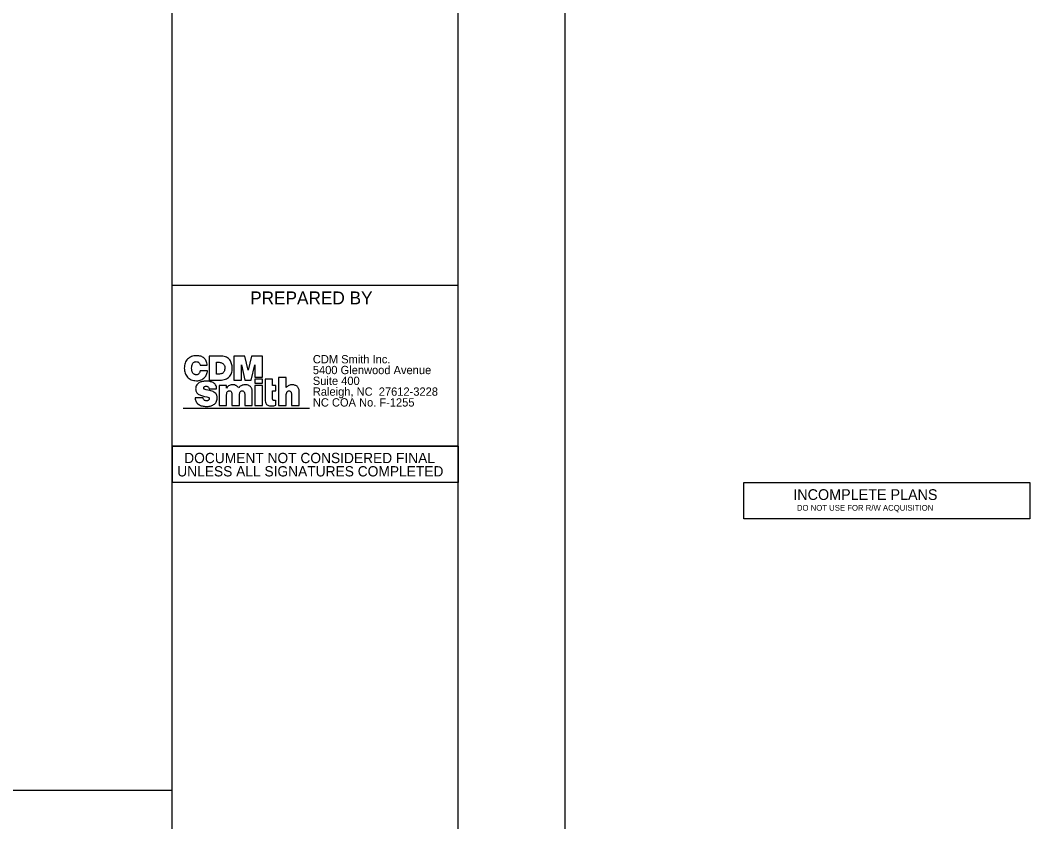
# Model space of a CAD drawing. Extents: x 24 to 1886, y 15 to 1115.
# Drawn here: x 1533.3 to 1886.4, y 554 to 834.5 of the extents above; entities that cross this region are included whole.
import ezdxf

# ---------------------------------------------------------------- set-up
doc = ezdxf.new("R2010")
doc.units = 0
for name, color, linetype in [('Sheet Block Title CELL', 7, 'Continuous'), ('Sheet_Plan_CELL', 7, 'Continuous'), ('z - Construction', 7, 'Continuous')]:
    doc.layers.add(name, color=color, linetype=linetype)

msp = doc.modelspace()

# ---------------------------------------------------------------- linework, layer by layer
at = {"layer": 'Sheet Block Title CELL'}
msp.add_line((1590.3, 698.7), (1634.47, 698.7), dxfattribs=at)
for points in [[(1593.57, 711.15), (1593.49, 711.32), (1593.43, 711.49), (1593.32, 711.89), (1593.26, 712.28), (1593.23, 712.71), (1593.26, 713.14), (1593.32, 713.53), (1593.43, 713.93), (1593.49, 714.1), (1593.57, 714.27), (1593.69, 714.44), (1593.8, 714.59), (1593.91, 714.7), (1594.09, 714.81), (1594.23, 714.9), (1594.43, 714.96), (1594.62, 714.98), (1594.82, 715.01), (1595.02, 714.98), (1595.19, 714.96), (1595.34, 714.93), (1595.48, 714.87), (1595.62, 714.78), (1595.7, 714.7), (1595.88, 714.5), (1596.02, 714.3), (1596.1, 714.1), (1596.16, 713.9), (1596.19, 713.79), (1598.69, 713.79), (1598.63, 714.16), (1598.55, 714.53), (1598.46, 714.87), (1598.32, 715.18), (1598.18, 715.47), (1598.01, 715.75), (1597.81, 716.01), (1597.58, 716.21), (1597.32, 716.4), (1597.04, 716.6), (1596.76, 716.75), (1596.44, 716.86), (1596.07, 716.97), (1595.7, 717.03), (1595.31, 717.09), (1594.91, 717.09), (1594.43, 717.09), (1593.97, 717), (1593.55, 716.92), (1593.15, 716.77), (1592.78, 716.6), (1592.44, 716.4), (1592.1, 716.15), (1591.81, 715.89), (1591.56, 715.58), (1591.33, 715.27), (1591.13, 714.9), (1590.96, 714.5), (1590.82, 714.1), (1590.73, 713.65), (1590.68, 713.19), (1590.65, 712.71), (1590.68, 712.26), (1590.73, 711.8), (1590.82, 711.38), (1590.93, 710.98), (1591.1, 710.61), (1591.27, 710.24), (1591.5, 709.9), (1591.75, 709.59), (1592.04, 709.3), (1592.38, 709.07), (1592.72, 708.85), (1593.09, 708.68), (1593.49, 708.53), (1593.94, 708.42), (1594.4, 708.36), (1594.91, 708.33), (1595.34, 708.33), (1595.76, 708.42), (1596.16, 708.51), (1596.53, 708.65), (1596.87, 708.79), (1597.18, 708.99), (1597.47, 709.19), (1597.72, 709.44), (1597.95, 709.7), (1598.15, 709.95), (1598.32, 710.27), (1598.46, 710.55), (1598.57, 710.86), (1598.66, 711.18), (1598.72, 711.49), (1598.72, 711.8), (1596.19, 711.8), (1596.13, 711.52), (1596.05, 711.26), (1595.93, 711.03), (1595.79, 710.81), (1595.59, 710.64), (1595.39, 710.52), (1595.14, 710.44), (1594.82, 710.41), (1594.62, 710.44), (1594.43, 710.47), (1594.23, 710.52), (1594.08, 710.61), (1593.91, 710.72), (1593.8, 710.84), (1593.69, 710.98), (1593.57, 711.15)], [(1607.41, 712.26), (1607.41, 712.71), (1607.41, 713.11), (1607.38, 713.51), (1607.3, 713.9), (1607.21, 714.27), (1607.1, 714.61), (1606.96, 714.98), (1606.79, 715.3), (1606.59, 715.61), (1606.33, 715.89), (1606.08, 716.12), (1605.76, 716.35), (1605.42, 716.55), (1605.02, 716.69), (1604.6, 716.8), (1604.14, 716.86), (1603.63, 716.89), (1599.4, 716.89), (1599.4, 708.53), (1603.15, 708.53), (1603.66, 708.53), (1604.17, 708.59), (1604.63, 708.7), (1605.05, 708.82), (1605.42, 708.99), (1605.79, 709.19), (1606.1, 709.41), (1606.39, 709.67), (1606.62, 709.95), (1606.84, 710.27), (1607.01, 710.61), (1607.16, 710.98), (1607.27, 711.37), (1607.35, 711.8), (1607.41, 712.26)], [(1601.98, 714.76), (1602.81, 714.76), (1603.15, 714.73), (1603.43, 714.7), (1603.69, 714.61), (1603.92, 714.5), (1604.12, 714.39), (1604.29, 714.24), (1604.4, 714.1), (1604.51, 713.96), (1604.63, 713.79), (1604.68, 713.62), (1604.8, 713.28), (1604.83, 712.99), (1604.85, 712.77), (1604.83, 712.45), (1604.77, 712.11), (1604.68, 711.74), (1604.6, 711.57), (1604.51, 711.43), (1604.43, 711.26), (1604.29, 711.12), (1604.14, 711.01), (1603.97, 710.89), (1603.77, 710.81), (1603.55, 710.72), (1603.29, 710.69), (1603.01, 710.66), (1601.98, 710.66), (1601.98, 714.76)], [(1610.62, 713.9), (1610.68, 713.9), (1611.82, 708.53), (1614.09, 708.53), (1615.31, 713.9), (1615.37, 713.9), (1615.37, 709.58), (1618.01, 709.58), (1618.01, 716.89), (1614.2, 716.89), (1613.01, 711.97), (1612.98, 711.97), (1611.79, 716.89), (1608.01, 716.89), (1608.01, 708.53), (1610.62, 708.53), (1610.62, 713.9)], [(1602.18, 702.57), (1602.15, 702.79), (1602.1, 702.99), (1602.04, 703.22), (1601.96, 703.39), (1601.87, 703.56), (1601.76, 703.73), (1601.64, 703.87), (1601.36, 704.13), (1601.05, 704.36), (1600.73, 704.53), (1600.36, 704.67), (1599.99, 704.78), (1599.63, 704.87), (1598.89, 705.04), (1598.26, 705.15), (1598.01, 705.24), (1597.78, 705.32), (1597.66, 705.38), (1597.55, 705.46), (1597.47, 705.58), (1597.44, 705.75), (1597.47, 705.95), (1597.52, 706.09), (1597.61, 706.2), (1597.72, 706.29), (1597.86, 706.35), (1598.03, 706.37), (1598.35, 706.4), (1598.52, 706.37), (1598.69, 706.35), (1598.83, 706.26), (1598.97, 706.15), (1599.11, 706.03), (1599.23, 705.89), (1599.28, 705.72), (1599.31, 705.52), (1601.98, 705.52), (1601.96, 705.92), (1601.87, 706.26), (1601.76, 706.57), (1601.61, 706.86), (1601.42, 707.08), (1601.22, 707.31), (1600.99, 707.51), (1600.71, 707.65), (1600.45, 707.79), (1600.14, 707.91), (1599.85, 707.99), (1599.54, 708.08), (1599.2, 708.14), (1598.89, 708.16), (1598.26, 708.19), (1597.66, 708.16), (1597.35, 708.11), (1597.04, 708.08), (1596.73, 707.99), (1596.44, 707.91), (1596.16, 707.79), (1595.87, 707.65), (1595.62, 707.48), (1595.36, 707.28), (1595.16, 707.06), (1594.99, 706.83), (1594.85, 706.54), (1594.74, 706.23), (1594.65, 705.89), (1594.62, 705.49), (1594.65, 705.24), (1594.68, 704.98), (1594.74, 704.75), (1594.82, 704.53), (1594.91, 704.33), (1595.05, 704.13), (1595.19, 703.96), (1595.36, 703.79), (1595.56, 703.65), (1595.79, 703.5), (1596.05, 703.36), (1596.33, 703.25), (1596.64, 703.13), (1596.98, 703.02), (1597.78, 702.85), (1598.6, 702.68), (1598.89, 702.59), (1599.09, 702.51), (1599.23, 702.4), (1599.31, 702.28), (1599.37, 702.14), (1599.4, 701.97), (1599.37, 701.8), (1599.28, 701.66), (1599.17, 701.54), (1599.03, 701.46), (1598.89, 701.4), (1598.72, 701.34), (1598.4, 701.32), (1598.15, 701.34), (1597.92, 701.37), (1597.75, 701.46), (1597.61, 701.54), (1597.47, 701.71), (1597.35, 701.91), (1597.3, 702.08), (1597.27, 702.31), (1594.45, 702.31), (1594.48, 701.91), (1594.57, 701.54), (1594.68, 701.23), (1594.82, 700.92), (1594.99, 700.66), (1595.22, 700.41), (1595.45, 700.18), (1595.7, 700.01), (1595.99, 699.84), (1596.3, 699.7), (1596.61, 699.58), (1596.93, 699.5), (1597.27, 699.41), (1597.61, 699.38), (1597.95, 699.36), (1598.29, 699.33), (1599, 699.36), (1599.34, 699.41), (1599.68, 699.47), (1600.02, 699.55), (1600.34, 699.67), (1600.65, 699.78), (1600.93, 699.95), (1601.22, 700.12), (1601.44, 700.35), (1601.67, 700.58), (1601.84, 700.86), (1601.98, 701.17), (1602.1, 701.52), (1602.18, 701.88), (1602.18, 702.31), (1602.18, 702.57)], [(1605.54, 703.99), (1605.59, 704.19), (1605.71, 704.38), (1605.82, 704.53), (1605.96, 704.64), (1606.16, 704.73), (1606.42, 704.75), (1606.67, 704.73), (1606.9, 704.64), (1607.04, 704.53), (1607.16, 704.36), (1607.21, 704.16), (1607.27, 703.96), (1607.3, 703.73), (1607.3, 703.48), (1607.3, 699.67), (1609.97, 699.67), (1609.97, 703.48), (1610, 703.73), (1610.03, 703.99), (1610.08, 704.19), (1610.2, 704.38), (1610.31, 704.53), (1610.45, 704.64), (1610.65, 704.73), (1610.91, 704.75), (1611.16, 704.73), (1611.39, 704.64), (1611.53, 704.53), (1611.64, 704.36), (1611.7, 704.16), (1611.76, 703.96), (1611.79, 703.73), (1611.79, 703.48), (1611.79, 699.67), (1614.46, 699.67), (1614.46, 704.5), (1614.43, 704.92), (1614.4, 705.15), (1614.34, 705.35), (1614.29, 705.55), (1614.17, 705.75), (1614.06, 705.95), (1613.95, 706.12), (1613.78, 706.29), (1613.61, 706.43), (1613.41, 706.57), (1613.18, 706.69), (1612.95, 706.77), (1612.67, 706.83), (1612.38, 706.89), (1612.04, 706.89), (1611.73, 706.89), (1611.45, 706.86), (1611.19, 706.8), (1610.93, 706.74), (1610.74, 706.66), (1610.54, 706.57), (1610.22, 706.37), (1610, 706.17), (1609.83, 706), (1609.66, 705.78), (1609.49, 706.03), (1609.31, 706.26), (1609.09, 706.46), (1608.86, 706.6), (1608.58, 706.71), (1608.32, 706.83), (1608.04, 706.89), (1607.72, 706.89), (1607.38, 706.89), (1607.04, 706.83), (1606.73, 706.74), (1606.42, 706.63), (1606.13, 706.49), (1605.88, 706.29), (1605.65, 706.06), (1605.39, 705.74), (1605.39, 706.71), (1602.81, 706.71), (1602.81, 699.67), (1605.48, 699.67), (1605.48, 703.48), (1605.51, 703.73), (1605.54, 703.99)], [(1618.01, 708.87), (1615.37, 708.87), (1615.37, 707.42), (1618.01, 707.42), (1618.01, 708.87)], [(1618.01, 706.71), (1615.37, 706.71), (1615.37, 699.64), (1618.01, 699.64), (1618.01, 706.71)], [(1622.7, 706.71), (1621.53, 706.71), (1621.53, 708.87), (1618.92, 708.87), (1618.92, 706.71), (1618.92, 704.73), (1618.92, 702.25), (1618.92, 701.71), (1618.98, 701.23), (1619.06, 700.83), (1619.17, 700.49), (1619.32, 700.24), (1619.46, 700.04), (1619.66, 699.89), (1619.86, 699.75), (1620.11, 699.64), (1620.42, 699.55), (1620.79, 699.5), (1621.25, 699.5), (1621.56, 699.5), (1621.93, 699.55), (1622.33, 699.61), (1622.7, 699.72), (1622.7, 701.49), (1622.58, 701.46), (1622.39, 701.43), (1621.99, 701.4), (1621.85, 701.43), (1621.73, 701.51), (1621.67, 701.57), (1621.62, 701.63), (1621.59, 701.71), (1621.56, 701.86), (1621.53, 702.22), (1621.53, 704.73), (1622.7, 704.73), (1622.7, 706.71)], [(1630.74, 705.35), (1630.63, 705.61), (1630.54, 705.83), (1630.4, 706.03), (1630.26, 706.2), (1630.09, 706.37), (1629.92, 706.49), (1629.72, 706.6), (1629.49, 706.71), (1629.26, 706.77), (1629.03, 706.83), (1628.78, 706.86), (1628.52, 706.88), (1628.18, 706.86), (1627.87, 706.83), (1627.56, 706.77), (1627.22, 706.63), (1626.99, 706.49), (1626.79, 706.34), (1626.56, 706.15), (1626.33, 705.92), (1626.33, 709.5), (1623.61, 709.5), (1623.61, 699.64), (1626.33, 699.64), (1626.33, 703.05), (1626.33, 703.47), (1626.39, 703.87), (1626.51, 704.16), (1626.56, 704.27), (1626.62, 704.38), (1626.73, 704.53), (1626.9, 704.64), (1627.07, 704.73), (1627.24, 704.75), (1627.47, 704.75), (1627.64, 704.7), (1627.78, 704.61), (1627.93, 704.47), (1628.04, 704.33), (1628.1, 704.1), (1628.15, 703.84), (1628.15, 703.53), (1628.15, 699.64), (1630.88, 699.64), (1630.88, 704.13), (1630.88, 704.47), (1630.85, 704.78), (1630.8, 705.09), (1630.74, 705.35)]]:
    msp.add_lwpolyline(points, dxfattribs=at)
at = {"layer": 'Sheet_Plan_CELL'}
for p, q in [((1586.43, 52.48), (1586.45, 1077.48)), ((1686.43, 52.48), (1686.45, 1077.48)), ((1686.42, 741.61), (1586.43, 741.61)), ((1686.48, 685.42), (1586.48, 685.42)), ((1586.44, 564.98), (61.45, 564.98))]:
    msp.add_line(p, q, dxfattribs=at)
for points in [[(1586.48, 685.42), (1686.48, 685.42), (1686.48, 672.68), (1586.48, 672.68)], [(1786.44, 672.68), (1886.44, 672.68), (1886.44, 659.94), (1786.44, 659.94)]]:
    msp.add_lwpolyline(points, close=True, dxfattribs=at)
at = {"layer": 'z - Construction'}
msp.add_line((1723.95, 14.98), (1723.95, 1114.98), dxfattribs=at)

# ---------------------------------------------------------------- texts
at = {"layer": 'Sheet Block Title CELL'}
for s, height, p in [('CDM Smith Inc.', 2.9003, (1635.63, 714.4)), ('5400 Glenwood Avenue', 2.9003, (1635.63, 710.62)), ('Suite 400', 2.9, (1635.63, 706.84)), ('Raleigh, NC  27612-3228', 2.9003, (1635.63, 703.07)), ('NC COA No. F-1255', 2.9003, (1635.63, 699.29))]:
    msp.add_text(s, height=height, rotation=359.9982, dxfattribs=at).set_placement(p)
at = {"layer": 'Sheet_Plan_CELL'}
for s, height, p in [('PREPARED BY', 4.5, (1613.71, 735.06)), ('DOCUMENT NOT CONSIDERED FINAL', 3.6, (1590.63, 679.49)), ('UNLESS ALL SIGNATURES COMPLETED', 3.6, (1588.2, 674.83))]:
    msp.add_text(s, height=height, rotation=0, dxfattribs=at).set_placement(p)
for s, height, p in [('INCOMPLETE PLANS', 3.75, (1803.71, 666.61)), ('DO NOT USE FOR R/W ACQUISITION', 2.025, (1804.97, 662.84))]:
    msp.add_text(s, height=height, dxfattribs=at).set_placement(p)

doc.saveas('drawing.dxf')
